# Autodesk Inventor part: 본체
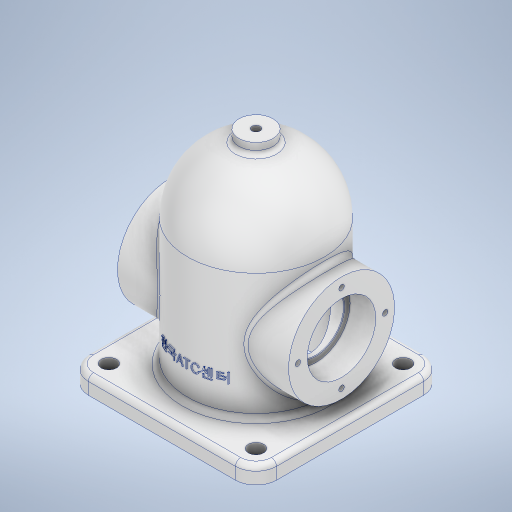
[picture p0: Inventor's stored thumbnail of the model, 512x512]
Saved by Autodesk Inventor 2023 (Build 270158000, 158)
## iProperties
Created: 2025-04
Part Number: 본체
Material: 알루미늄 6061
Document SubType Name: Modeling
Designer: User
Density: 2.7 g/cm^3
Appearance: 알루미늄 - 평지
Author: User
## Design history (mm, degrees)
sketch "스케치1"
  geometry: L1 (-55, 55)-(55, 55); L2 (55, 55)-(55, -55); L3 (55, -55)-(-55, -55); L4 (-55, -55)-(-55, 55); L5 (-55, 55)-(55, -55); L6 (55, 55)-(-55, -55); 1 further point
  constraints: 12 end point, 2 midpoint, 2 parallel, 1 horizontal, 1 perpendicular
  dimensions: "d0" = 110 distance of L2.end L3.end; "d1" = 110 distance of L1.end L2.end
extrude "돌출1" new body sketch "스케치1" distance "d2" = 10; taper "d3" = 0 deg
fillet "모깎기1" dims "d4" = 3
sketch "스케치2"
  geometry: C1 r 40 at (0, 0); 1 further point
  constraints: 1 centre point, 1 coincident
  dimensions: "d5" = 80 diameter of C1
extrude "돌출2" join sketch "스케치2" distance "d6" = 84; taper "d7" = 0 deg
node "작업 평면1"
sketch "스케치3"
  geometry: L1 (55, 0)-(-55, 0) reference; C1 r 31 at (0, 48); 1 further point
  constraints: 1 centre point, 1 vertical alignment
  dimensions: "d9" = 62 diameter of C1; "d10" = 48 distance from line of L1 C1.centre
extrude "돌출3" join sketch "스케치3" stored distance "d11" = 84; taper "d12" = 0 deg
sketch "스케치4" dims "d13" = 51
  geometry: L1 (-55, -48)-(55, -48) reference; 4 further points
  constraints: 3 vertical alignment, 1 midpoint, 2 other
  dimensions: "d14" = 48 distance from line of L1 point (0, 0)
hole "구멍1" sketch "스케치4" at (0, 25.5) diameter "d15" = 3.242; stored, may be unused: countersink angle "d19" = 90 deg, drill point angle "d21" = 118 deg; dims "d16" = 8, "d17" = 4, "d18" = 2, "d20" = 10
sketch "스케치5"
  geometry: L1 (84, -40)-(84, 40) reference; A1 r 40 centre (84, 0) between (84, -40) and (84, 40); 1 further point
  constraints: 2 point on circle, 1 centre point, 1 midpoint
revolve "회전1" sketch "스케치5" stored, may be unused: angle "d25" = 90 deg
sketch "스케치6"
  geometry: C1 r 32 at (0, 0); 1 further point
  constraints: 1 centre point, 1 coincident
  dimensions: "d26" = 64 diameter of C1
extrude "돌출4" cut sketch "스케치6" distance "d27" = 84; taper "d28" = 0 deg
sketch "스케치7"
  geometry: L1 (84, -32)-(84, 32) reference; A1 r 32 centre (84, 0) between (84, -32) and (84, 32); 2 further points
  constraints: 2 point on circle, 1 centre point, 1 midpoint
revolve "회전2" sketch "스케치7" stored, may be unused: angle "d29" = 90 deg
sketch "스케치8"
  geometry: L1 (-55, -48)-(55, -48) reference; C1 r 16.5 at (0, 0); 2 further points
  constraints: 1 centre point, 1 midpoint, 1 vertical alignment
  dimensions: "d30" = 33 diameter of C1; "d31" = 48 distance from line of L1 C1.centre
extrude "돌출5" cut sketch "스케치8" stored distance "d32" = 15; taper "d33" = 0 deg
node "작업 평면2"
fillet "모깎기2" dims "d45" = 3
fillet "모깎기3" dims "d46" = 3
sketch "스케치11"
  geometry: L1 (43, -43)-(-43, -43); L2 (-43, -43)-(-43, 43); L3 (-43, 43)-(43, 43); L4 (43, 43)-(43, -43); L5 (43, -43)-(-43, 43); L6 (-43, -43)-(43, 43); 5 further points
  constraints: 12 end point, 4 coincident, 2 midpoint, 2 parallel, 1 horizontal, 1 perpendicular
  dimensions: "d47" = 86 distance of L2.end L3.end; "d48" = 86 distance of L1.end L2.end
hole "구멍3" sketch "스케치11" at (-43, -43), (-43, 43), (43, 43), (43, -43) diameter "d49" = 9; stored, may be unused: countersink angle "d53" = 90 deg, drill point angle "d55" = 118 deg; dims "d50" = 6, "d51" = 4, "d52" = 2, "d54" = 13
fillet "모깎기4" dims "d56" = 12
chamfer "모따기1" distance "d57" = 1; stored, may be unused: second distance "d58" = 2, angle "d59" = 45 deg
node "작업 평면3"
sketch "스케치12"
  geometry: C1 r 10 at (0, 0); 1 further point
  constraints: 1 centre point, 1 coincident
  dimensions: "d64" = 20 diameter of C1
extrude "돌출7" join sketch "스케치12" stored distance "d65" = 10; taper "d66" = 0 deg
fillet "모깎기5" dims "d67" = 3
sketch "스케치13"
  geometry: C1 r 10 at (0, 0) reference; 2 further points
  constraints: 1 coincident
hole "구멍4" sketch "스케치13" diameter "d69" = 4.917; stored, may be unused: countersink angle "d73" = 82 deg, drill point angle "d75" = 0 deg; dims "d70" = 13, "d71" = 3.023, "d72" = 2, "d74" = 13
node "작업 평면5"
sketch "스케치15"
  geometry: L1 (0, 43)-(0, -43) reference; 3 further points
  constraints: 1 horizontal alignment, 1 midpoint, 1 other
  dimensions: "d77" = 30 distance from line of L1 point (30, 0)
feature "엠보싱1" sketch "스케치15" dims "d0" = 110, "d1" = 110, "d78" = 0.5, "d79" = 0
sketch "스케치17"
  geometry: L1 (-43, -48)-(43, -48) reference; C1 r 20 at (0, 0); 2 further points
  constraints: 1 centre point, 1 midpoint, 1 vertical alignment
  dimensions: "d81" = 40 diameter of C1; "d82" = 48 distance from line of L1 C1.centre
extrude "돌출8" cut sketch "스케치17" distance "d83" = 15; taper "d84" = 0 deg
chamfer "모따기3" distance "d85" = 0.3; stored, may be unused: second distance "d86" = 2, angle "d87" = 45 deg
node "솔리드1"
mirror "미러1"
pattern_circular "원형 패턴1" dims angle "d23" = 360 deg
mirror "미러2"
mirror "미러3"
feature "A9D066F2-1C7D-4E18-AEED-F7BC21143FA4" dims "d49" = 9, "d50" = 6, "d51" = 4, "d52" = 2, "d53" = 90 deg, "d54" = 13, "d55" = 118 deg
other parameters: "d34" = 124, "d63" = 129
